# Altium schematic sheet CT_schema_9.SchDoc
size 147 x 119 mm
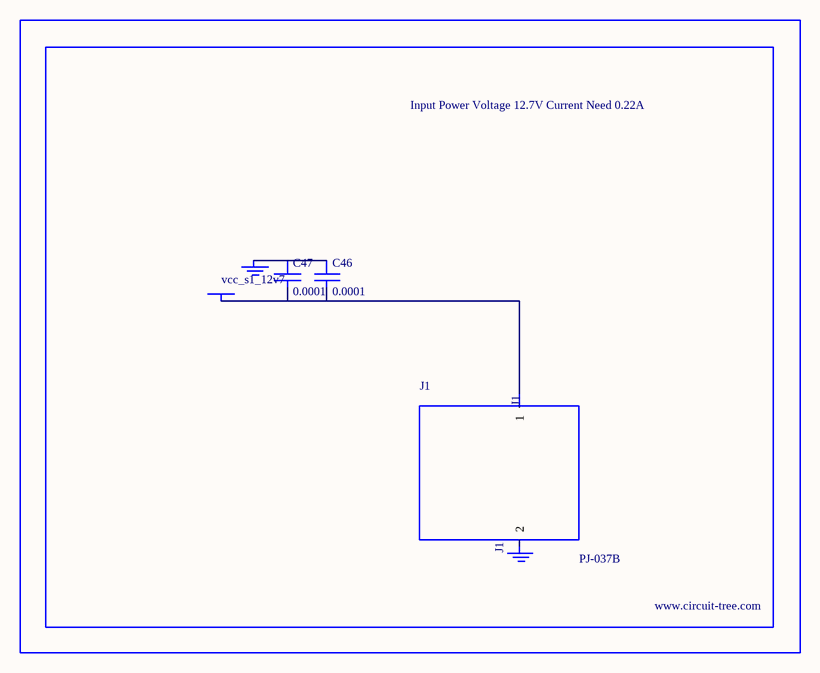
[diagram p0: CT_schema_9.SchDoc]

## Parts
BORDER8  (no value)
C46  0.0001  [EXV-9H]
C47  0.0001  [EXV-9H]
GND_INSTANCE_8_0  (no value)
GND_INSTANCE_8_1  (no value)
J1  PJ-037B  [PJ-037B_PACKAGE]
POWER_INSTANCE_8_0  vcc_s1_12v7

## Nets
NetC46_1: C46.1 C47.1 GND_INSTANCE_8_0.0(GND)
NetC46_2: C46.2 C47.2 J1.1 POWER_INSTANCE_8_0.0(PWR)

Not connected (* = marked no-connect by the designer): GND_INSTANCE_8_1 0(GND); J1 2

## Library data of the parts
BORDER8 = BORDER_PAGE8
C46 C47 = EDK107M035A9HAA
GND_INSTANCE_8_0 GND_INSTANCE_8_1 = GND
POWER_INSTANCE_8_0 = PWR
